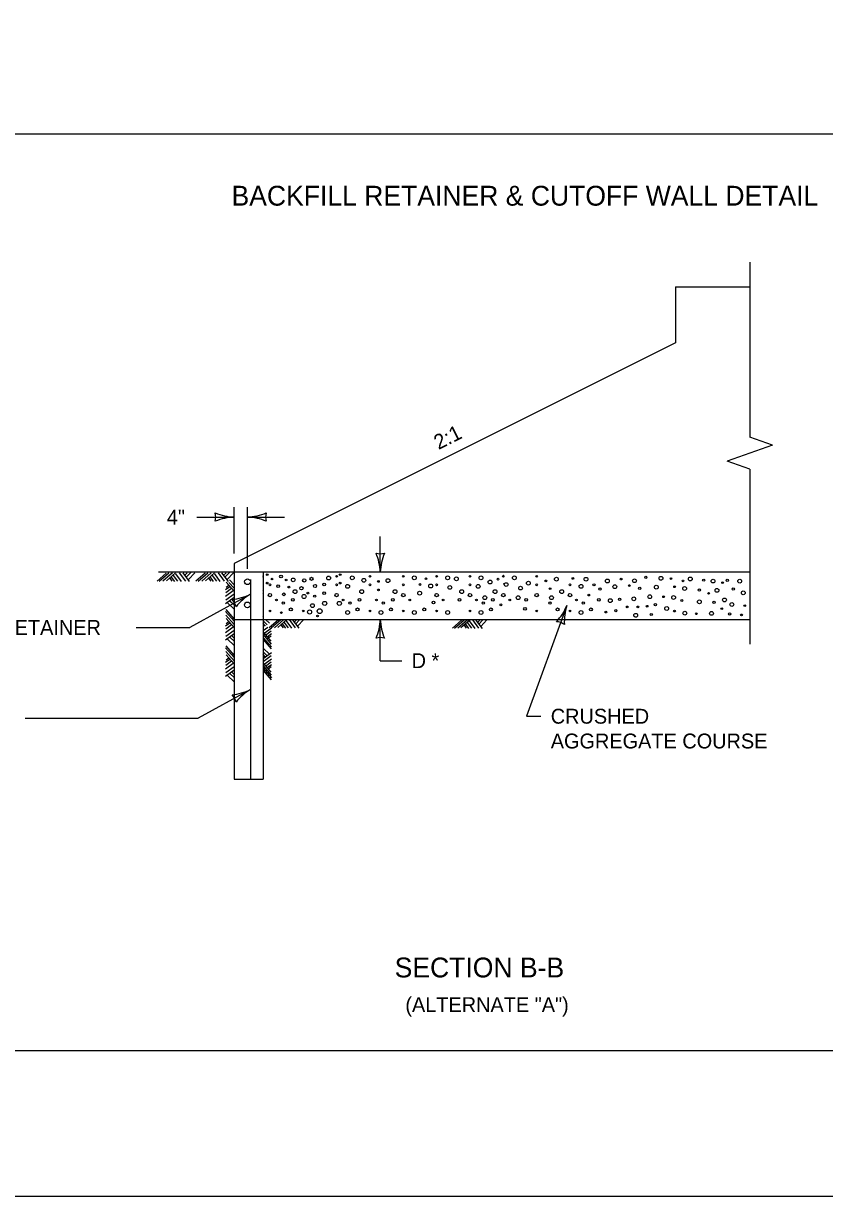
# Model space of a CAD drawing. Extents: x 49991.4 to 50021, y 49987.6 to 50011.4.
# Drawn here: x 50003.791 to 50007.022, y 49987.799 to 49992.532 of the extents above; entities that cross this region are included whole.
import ezdxf

# ---------------------------------------------------------------- set-up
doc = ezdxf.new("R2010")
doc.units = 0
for name, color, linetype in [('Level 1', 7, 'Continuous'), ('Level 2', 7, 'Continuous'), ('Level 3', 7, 'Continuous'), ('Level 6', 7, 'Continuous')]:
    doc.layers.add(name, color=color, linetype=linetype)

msp = doc.modelspace()

# ---------------------------------------------------------------- linework, layer by layer
at = {"layer": 'Level 1'}
for p, q in [((50006.4202, 49991.4692), (50006.4202, 49991.2434)), ((50006.4202, 49991.4692), (50006.7199, 49991.4692)), ((50006.4202, 49991.2434), (50004.6404, 49990.3535)), ((50004.6404, 49990.3535), (50004.6404, 49989.4831)), ((50004.367, 49990.3145), (50004.33, 49990.2823)), ((50004.3363, 49990.3188), (50004.7574, 49990.3188)), ((50004.3779, 49990.3145), (50004.339, 49990.2806)), ((50004.3917, 49990.3147), (50004.3537, 49990.2816)), ((50004.4049, 49990.3149), (50004.3686, 49990.2833)), ((50004.3814, 49990.2939), (50004.3899, 49990.2822)), ((50004.3876, 49990.2978), (50004.4001, 49990.2806)), ((50004.3954, 49990.305), (50004.4127, 49990.2812)), ((50004.405, 49990.3115), (50004.4276, 49990.2806)), ((50004.4197, 49990.3153), (50004.4442, 49990.2816)), ((50004.434, 49990.3155), (50004.46, 49990.2798)), ((50004.441, 49990.304), (50004.4518, 49990.3155)), ((50004.4475, 49990.2972), (50004.4658, 49990.3165)), ((50004.457, 49990.2881), (50004.4824, 49990.3151)), ((50004.5234, 49990.3145), (50004.4863, 49990.2823)), ((50004.5343, 49990.3145), (50004.4954, 49990.2806)), ((50004.5481, 49990.3147), (50004.51, 49990.2816)), ((50004.5613, 49990.3149), (50004.5248, 49990.2833)), ((50004.5378, 49990.2939), (50004.5463, 49990.2822)), ((50004.544, 49990.2978), (50004.5565, 49990.2806)), ((50004.5517, 49990.305), (50004.5691, 49990.2812)), ((50004.5613, 49990.3115), (50004.5838, 49990.2806)), ((50004.5759, 49990.3153), (50004.6005, 49990.2816)), ((50004.5902, 49990.3155), (50004.6164, 49990.2798)), ((50004.5973, 49990.304), (50004.6081, 49990.3155)), ((50004.6038, 49990.2972), (50004.622, 49990.3165)), ((50004.6134, 49990.2881), (50004.6388, 49990.3151)), ((50004.6404, 49990.2662), (50004.6222, 49990.2871)), ((50004.6404, 49990.3145), (50004.6404, 49990.3145)), ((50004.7072, 49990.2888), (50004.7072, 49989.4831)), ((50004.7574, 49990.3188), (50004.7574, 49989.4831)), ((50004.7574, 49990.3188), (50006.7199, 49990.3188)), ((50004.7574, 49990.3145), (50004.7574, 49990.3145)), ((50004.6236, 49990.2588), (50004.6065, 49990.2462)), ((50004.6374, 49990.2428), (50004.6065, 49990.2203)), ((50004.6308, 49990.2516), (50004.607, 49990.2343)), ((50004.6197, 49990.2644), (50004.6081, 49990.2559)), ((50004.6408, 49990.241), (50004.6092, 49990.2774)), ((50004.6406, 49990.2534), (50004.6201, 49990.2769)), ((50004.6414, 49990.2157), (50004.6057, 49990.1897)), ((50004.6411, 49990.2291), (50004.6075, 49990.2045)), ((50004.614, 49990.1941), (50004.6408, 49990.1687)), ((50004.6231, 49990.2029), (50004.6424, 49990.1845)), ((50004.6238, 49990.2012), (50004.6352, 49990.1904)), ((50004.6299, 49990.2086), (50004.6413, 49990.1978)), ((50004.6404, 49990.1197), (50004.6065, 49990.1586)), ((50004.6406, 49990.1067), (50004.6075, 49990.1448)), ((50004.6404, 49990.13), (50004.6081, 49990.167)), ((50004.6236, 49990.1123), (50004.6065, 49990.0997)), ((50004.6374, 49990.0962), (50004.6065, 49990.0736)), ((50004.6308, 49990.1051), (50004.607, 49990.0878)), ((50004.6197, 49990.1179), (50004.6081, 49990.1094)), ((50004.6408, 49990.0945), (50004.6092, 49990.1309)), ((50004.6404, 49990.1273), (50006.7199, 49990.1273)), ((50004.7746, 49990.1049), (50004.7574, 49990.1212)), ((50004.7678, 49990.1005), (50004.7574, 49990.1104)), ((50004.7574, 49990.0826), (50004.7763, 49990.0964)), ((50004.7838, 49990.1119), (50004.7675, 49990.1273)), ((50004.8194, 49990.1262), (50004.7824, 49990.0939)), ((50004.8292, 49990.1262), (50004.7903, 49990.0922)), ((50004.8415, 49990.1263), (50004.8034, 49990.0932)), ((50004.8531, 49990.1266), (50004.8167, 49990.0948)), ((50004.8297, 49990.1055), (50004.8382, 49990.0939)), ((50004.8351, 49990.1094), (50004.8476, 49990.0922)), ((50004.8417, 49990.1166), (50004.859, 49990.0928)), ((50004.85, 49990.1232), (50004.8725, 49990.0923)), ((50004.8629, 49990.1269), (50004.8874, 49990.0933)), ((50004.8755, 49990.1271), (50004.9016, 49990.0915)), ((50004.8826, 49990.1157), (50004.8934, 49990.1271)), ((50004.888, 49990.1088), (50004.9055, 49990.1273)), ((50004.8961, 49990.0996), (50004.9216, 49990.1266)), ((50005.5583, 49990.1248), (50005.5213, 49990.0925)), ((50005.5681, 49990.1248), (50005.5292, 49990.0908)), ((50005.5804, 49990.1249), (50005.5423, 49990.0918)), ((50005.592, 49990.1252), (50005.5556, 49990.0934)), ((50005.5687, 49990.1041), (50005.5771, 49990.0925)), ((50005.574, 49990.108), (50005.5865, 49990.0908)), ((50005.5806, 49990.1152), (50005.598, 49990.0914)), ((50005.5889, 49990.1218), (50005.6114, 49990.0909)), ((50005.6018, 49990.1255), (50005.6264, 49990.0919)), ((50005.6146, 49990.1257), (50005.6406, 49990.0901)), ((50005.6216, 49990.1143), (50005.6324, 49990.1257)), ((50005.6269, 49990.1074), (50005.6453, 49990.1268)), ((50005.6351, 49990.0982), (50005.6605, 49990.1252)), ((50004.6414, 49990.0692), (50004.6057, 49990.0431)), ((50004.6411, 49990.0825), (50004.6075, 49990.058)), ((50004.614, 49990.0476), (50004.6408, 49990.0221)), ((50004.6231, 49990.0562), (50004.6424, 49990.038)), ((50004.6299, 49990.0621), (50004.6413, 49990.0513)), ((50004.7574, 49990.0758), (50004.7886, 49990.04)), ((50004.7574, 49990.0658), (50004.7902, 49990.028)), ((50004.7574, 49990.055), (50004.7912, 49990.0163)), ((50004.7574, 49990.0461), (50004.7896, 49990.0092)), ((50004.7604, 49990.0706), (50004.7912, 49990.0931)), ((50004.767, 49990.0634), (50004.7907, 49990.0807)), ((50004.7742, 49990.0577), (50004.7912, 49990.0701)), ((50004.778, 49990.0531), (50004.7896, 49990.0616)), ((50004.6404, 49989.9732), (50004.6065, 49990.0121)), ((50004.6404, 49989.9835), (50004.6081, 49990.0205)), ((50004.7838, 49989.9869), (50004.7574, 49990.0118)), ((50004.6236, 49989.9656), (50004.6065, 49989.9531)), ((50004.6308, 49989.9585), (50004.607, 49989.9411)), ((50004.6406, 49989.9602), (50004.6075, 49989.9983)), ((50004.6197, 49989.9714), (50004.6081, 49989.9629)), ((50004.6408, 49989.948), (50004.6092, 49989.9843)), ((50004.7746, 49989.98), (50004.7574, 49989.9963)), ((50004.7574, 49989.9692), (50004.792, 49989.9944)), ((50004.7678, 49989.9756), (50004.7574, 49989.9855)), ((50004.7574, 49989.9577), (50004.7902, 49989.9817)), ((50004.7604, 49989.9456), (50004.7912, 49989.9681)), ((50004.767, 49989.9384), (50004.7907, 49989.9558)), ((50004.6414, 49989.9227), (50004.6057, 49989.8966)), ((50004.6374, 49989.9497), (50004.6065, 49989.9271)), ((50004.6411, 49989.936), (50004.6075, 49989.9115)), ((50004.6231, 49989.9097), (50004.6424, 49989.8915)), ((50004.6299, 49989.9156), (50004.6413, 49989.9048)), ((50004.7574, 49989.9509), (50004.7886, 49989.915)), ((50004.7574, 49989.9407), (50004.7902, 49989.903)), ((50004.7574, 49989.9301), (50004.7912, 49989.8912)), ((50004.7574, 49989.9212), (50004.7896, 49989.8841)), ((50004.7742, 49989.9327), (50004.7912, 49989.9452)), ((50004.778, 49989.9282), (50004.7896, 49989.9367)), ((50004.614, 49989.9011), (50004.6408, 49989.8755)), ((50004.6404, 49989.7217), (50004.6404, 49989.7217)), ((50004.6404, 49989.4831), (50004.7574, 49989.4831))]:
    msp.add_line(p, q, dxfattribs=at)
for points in [[(49999.3835, 49998.9992), (50016.7501, 49998.9992), (50016.7501, 49987.7988), (49999.3835, 49987.7988)], [(49999.5517, 49992.0867), (50014.5753, 49992.0867), (50014.5753, 49988.387), (49999.5517, 49988.387)]]:
    msp.add_lwpolyline(points, close=True, dxfattribs=at)
for centre, radius in [((50004.6948, 49990.2792), 0.0116), ((50004.7742, 49990.3081), 0.00346), ((50004.7936, 49990.2901), 0.00341), ((50004.8299, 49990.3001), 0.00552), ((50004.8503, 49990.2864), 0.00341), ((50004.8792, 49990.2867), 0.00765), ((50004.9236, 49990.2848), 0.00684), ((50004.9529, 49990.291), 0.00613), ((50005.0218, 49990.2942), 0.00765), ((50005.0542, 49990.3012), 0.00341), ((50005.0684, 49990.3081), 0.00346), ((50005.1172, 49990.2951), 0.00766), ((50005.1639, 49990.2852), 0.00765), ((50005.1886, 49990.3012), 0.00341), ((50005.2226, 49990.2807), 0.00346), ((50005.261, 49990.2838), 0.00765), ((50005.3231, 49990.3012), 0.00341), ((50005.3675, 49990.2951), 0.00766), ((50005.4145, 49990.2912), 0.00341), ((50005.4575, 49990.3012), 0.00341), ((50005.5019, 49990.2951), 0.00766), ((50005.5371, 49990.291), 0.00765), ((50005.5919, 49990.3012), 0.00341), ((50005.6363, 49990.2951), 0.00766), ((50005.6729, 49990.2781), 0.00765), ((50005.7049, 49990.2897), 0.00341), ((50005.7264, 49990.3012), 0.00341), ((50005.7708, 49990.2951), 0.00766), ((50005.8608, 49990.3012), 0.00341), ((50005.8978, 49990.2828), 0.00341), ((50005.9404, 49990.2895), 0.00765), ((50006.0067, 49990.2926), 0.00341), ((50006.0597, 49990.2894), 0.00766), ((50006.1459, 49990.2823), 0.00766), ((50006.2015, 49990.2898), 0.00341), ((50006.2551, 49990.2833), 0.00766), ((50006.301, 49990.297), 0.0046), ((50006.3619, 49990.2931), 0.00766), ((50006.4025, 49990.2921), 0.00341), ((50006.451, 49990.2826), 0.00341), ((50006.4803, 49990.2905), 0.00766), ((50006.5344, 49990.2857), 0.0046), ((50006.5719, 49990.2819), 0.00766), ((50006.6292, 49990.2845), 0.0046), ((50006.6795, 49990.2818), 0.00766), ((50004.7742, 49990.2737), 0.00346), ((50004.7853, 49990.2668), 0.00341), ((50004.8184, 49990.2614), 0.00552), ((50004.8618, 49990.2577), 0.00341), ((50004.8864, 49990.2393), 0.00765), ((50004.9122, 49990.2532), 0.00684), ((50004.9382, 49990.2334), 0.00341), ((50004.9672, 49990.2623), 0.00613), ((50005.0041, 49990.2678), 0.00552), ((50005.0041, 49990.2334), 0.00552), ((50005.0542, 49990.2668), 0.00341), ((50005.0684, 49990.2737), 0.00346), ((50005.0986, 49990.2607), 0.00766), ((50005.1553, 49990.2393), 0.00765), ((50005.1886, 49990.2668), 0.00341), ((50005.2226, 49990.2463), 0.00346), ((50005.2897, 49990.2393), 0.00765), ((50005.3231, 49990.2668), 0.00341), ((50005.389, 49990.2334), 0.00766), ((50005.3901, 49990.2682), 0.00341), ((50005.4334, 49990.2621), 0.00766), ((50005.4575, 49990.2668), 0.00341), ((50005.5105, 49990.2564), 0.00766), ((50005.5586, 49990.2393), 0.00765), ((50005.5919, 49990.2668), 0.00341), ((50005.6249, 49990.2607), 0.00766), ((50005.693, 49990.2393), 0.00765), ((50005.7378, 49990.2679), 0.00766), ((50005.7959, 49990.2537), 0.00765), ((50005.8274, 49990.2738), 0.00765), ((50005.8608, 49990.2668), 0.00341), ((50005.915, 49990.2512), 0.00341), ((50005.9619, 49990.2393), 0.00765), ((50005.9952, 49990.2668), 0.00341), ((50006.0397, 49990.2607), 0.00766), ((50006.0918, 49990.2668), 0.0046), ((50006.1161, 49990.2496), 0.0046), ((50006.1761, 49990.2594), 0.00766), ((50006.2344, 49990.264), 0.00341), ((50006.2766, 49990.2525), 0.0046), ((50006.3433, 49990.2573), 0.00766), ((50006.4168, 49990.2591), 0.00341), ((50006.4574, 49990.2518), 0.00766), ((50006.5171, 49990.2455), 0.0046), ((50006.5543, 49990.2324), 0.00341), ((50006.5877, 49990.2446), 0.00766), ((50006.6102, 49990.2755), 0.00341), ((50006.6535, 49990.25), 0.0046), ((50006.6939, 49990.2345), 0.00766), ((50004.6944, 49990.1858), 0.0116), ((50004.7853, 49990.2256), 0.00684), ((50004.8114, 49990.2058), 0.00341), ((50004.8389, 49990.1935), 0.0046), ((50004.8412, 49990.2286), 0.00552), ((50004.8772, 49990.2058), 0.00552), ((50004.9229, 49990.2197), 0.00824), ((50004.9566, 49990.183), 0.00766), ((50004.9658, 49990.2212), 0.0046), ((50005.0061, 49990.192), 0.00824), ((50005.0542, 49990.2256), 0.00684), ((50005.0649, 49990.192), 0.00824), ((50005.0802, 49990.2058), 0.00341), ((50005.1078, 49990.1935), 0.0046), ((50005.1461, 49990.2058), 0.00552), ((50005.2147, 49990.2058), 0.00341), ((50005.2422, 49990.1935), 0.0046), ((50005.2805, 49990.2058), 0.00552), ((50005.3231, 49990.2256), 0.00684), ((50005.3491, 49990.2058), 0.00341), ((50005.445, 49990.1952), 0.00552), ((50005.4575, 49990.2256), 0.00684), ((50005.4835, 49990.2058), 0.00341), ((50005.5494, 49990.2058), 0.00552), ((50005.5919, 49990.2256), 0.00684), ((50005.618, 49990.2058), 0.00341), ((50005.6455, 49990.1935), 0.0046), ((50005.6517, 49990.2149), 0.00766), ((50005.6838, 49990.2058), 0.00552), ((50005.7165, 49990.1861), 0.00341), ((50005.7264, 49990.2256), 0.00684), ((50005.7524, 49990.2058), 0.00341), ((50005.7861, 49990.2149), 0.00766), ((50005.8183, 49990.2058), 0.00552), ((50005.8608, 49990.2256), 0.00684), ((50005.9144, 49990.1935), 0.0046), ((50005.9205, 49990.2149), 0.00766), ((50005.9952, 49990.2256), 0.00684), ((50006.0213, 49990.2058), 0.00341), ((50006.0488, 49990.1935), 0.0046), ((50006.0709, 49990.2253), 0.00341), ((50006.1114, 49990.2058), 0.00552), ((50006.1576, 49990.203), 0.00766), ((50006.1953, 49990.2087), 0.0046), ((50006.2523, 49990.2105), 0.00766), ((50006.3168, 49990.2188), 0.00766), ((50006.3397, 49990.1871), 0.0046), ((50006.3725, 49990.2185), 0.00341), ((50006.4129, 49990.2159), 0.00766), ((50006.4461, 49990.2037), 0.0046), ((50006.5168, 49990.1985), 0.00766), ((50006.5764, 49990.1957), 0.0046), ((50006.618, 49990.2059), 0.00766), ((50006.6478, 49990.1877), 0.00766), ((50004.7853, 49990.1615), 0.00341), ((50004.8313, 49990.1548), 0.00341), ((50004.8695, 49990.1676), 0.00613), ((50004.9198, 49990.1615), 0.00341), ((50004.945, 49990.1573), 0.00824), ((50004.9773, 49990.1413), 0.00341), ((50004.9858, 49990.1605), 0.00968), ((50005.0986, 49990.1554), 0.00766), ((50005.1384, 49990.1676), 0.00613), ((50005.1886, 49990.1615), 0.00341), ((50005.233, 49990.1554), 0.00766), ((50005.2729, 49990.1676), 0.00613), ((50005.3231, 49990.1615), 0.00341), ((50005.3675, 49990.1554), 0.00766), ((50005.4073, 49990.1676), 0.00613), ((50005.4575, 49990.1615), 0.00341), ((50005.5019, 49990.1554), 0.00766), ((50005.5919, 49990.1615), 0.00341), ((50005.6363, 49990.1554), 0.00766), ((50005.6762, 49990.1676), 0.00613), ((50005.8137, 49990.17), 0.00552), ((50005.8608, 49990.1615), 0.00341), ((50005.945, 49990.1676), 0.00613), ((50005.9952, 49990.1615), 0.00341), ((50006.0397, 49990.1554), 0.00766), ((50006.0795, 49990.1676), 0.00613), ((50006.14, 49990.1569), 0.00341), ((50006.1801, 49990.1627), 0.0046), ((50006.2258, 49990.1779), 0.00341), ((50006.2603, 49990.1439), 0.00766), ((50006.2689, 49990.1779), 0.00341), ((50006.306, 49990.1805), 0.00341), ((50006.3228, 49990.1471), 0.0046), ((50006.385, 49990.1711), 0.00766), ((50006.4166, 49990.1607), 0.00341), ((50006.4581, 49990.1523), 0.00766), ((50006.5044, 49990.1502), 0.00341), ((50006.566, 49990.1516), 0.00766), ((50006.6073, 49990.1708), 0.00341), ((50006.6387, 49990.1496), 0.0046), ((50006.6867, 49990.1455), 0.00341), ((50006.6998, 49990.1826), 0.00341)]:
    msp.add_circle(centre, radius, dxfattribs=at)
for centre, radius, start, end in [((50004.7556, 49990.3002), 0.0031, 305.1264, 54.8736), ((50005.7261, 49990.302), 0.00277, 77.9755, 102.0245), ((50004.752, 49990.2393), 0.00765, 314.8637, 45.1363), ((50005.7261, 49990.2675), 0.00277, 77.9755, 102.0245), ((50004.752, 49990.134), 0.00765, 316.4208, 45.1363)]:
    msp.add_arc(centre, radius, start, end, dxfattribs=at)
at = {"layer": 'Level 3'}
for p, q in [((50004.6404, 49990.3935), (50004.6404, 49990.5801)), ((50004.6945, 49990.3308), (50004.6945, 49990.5801)), ((50004.4904, 49990.5401), (50004.6404, 49990.5401)), ((50004.6945, 49990.5401), (50004.8445, 49990.5401)), ((50005.2301, 49990.3188), (50005.2301, 49990.4617)), ((50004.7072, 49990.2295), (50004.4629, 49990.095)), ((50005.9827, 49990.1839), (50005.8202, 49989.7367)), ((50004.2464, 49990.095), (50004.4629, 49990.095)), ((50005.2301, 49989.9608), (50005.2301, 49990.1273)), ((50005.2301, 49989.9608), (50005.3166, 49989.9608)), ((50004.7072, 49989.845), (50004.4957, 49989.7285)), ((50003.7984, 49989.7285), (50004.4957, 49989.7285)), ((50005.8202, 49989.7367), (50005.8776, 49989.7367))]:
    msp.add_line(p, q, dxfattribs=at)
for centre, radius, start, end in [((50004.6496, 49990.7622), 0.2223, 247.456, 267.6395), ((50004.5122, 49990.5401), 0.0548, 342.1388, 17.8612), ((50004.6519, 49990.3073), 0.233, 92.8273, 112.0772), ((50004.683, 49990.7728), 0.233, 272.8273, 292.0772), ((50004.6853, 49990.3179), 0.2223, 67.456, 87.6395), ((50004.8227, 49990.5401), 0.0548, 162.1388, 197.8612), ((50005.2301, 49990.447), 0.0548, 252.1388, 287.8612), ((50004.9974, 49990.3073), 0.233, 2.8273, 22.0772), ((50005.4522, 49990.3096), 0.2223, 157.456, 177.6395), ((50004.608, 49990.4285), 0.2223, 276.3053, 296.4888), ((50004.5949, 49990.1677), 0.0548, 10.9881, 46.7105), ((50004.8295, 49990.0312), 0.233, 121.6766, 140.9265), ((50005.777, 49990.2683), 0.2223, 317.4863, 337.6698), ((50006.2053, 49990.1152), 0.233, 162.8576, 182.1074), ((50005.008, 49990.1364), 0.2223, 337.456, 357.6395), ((50005.4628, 49990.1387), 0.233, 182.8273, 202.0772), ((50005.9389, 49990.0633), 0.0548, 52.1691, 87.8914), ((50005.2301, 49989.999), 0.0548, 72.1388, 107.8612), ((50004.608, 49990.0439), 0.2223, 276.3053, 296.4888), ((50004.5949, 49989.7831), 0.0548, 10.9881, 46.7105), ((50004.8295, 49989.6467), 0.233, 121.6766, 140.9265)]:
    msp.add_arc(centre, radius, start, end, dxfattribs=at)
at = {"layer": 'Level 6'}
for p, q in [((50006.7199, 49991.5692), (50006.7199, 49990.863)), ((50006.8113, 49990.8306), (50006.7199, 49990.863)), ((50006.8113, 49990.8306), (50006.7199, 49990.7982)), ((50006.7199, 49990.7982), (50006.6285, 49990.7658)), ((50006.7199, 49990.7334), (50006.6285, 49990.7658)), ((50006.7199, 49990.7334), (50006.7199, 49990.0273))]:
    msp.add_line(p, q, dxfattribs=at)

# ---------------------------------------------------------------- texts
at = {"layer": 'Level 2'}
for s, height, p in [('BACKFILL RETAINER & CUTOFF WALL DETAIL', 0.08, (50004.6304, 49991.7968)), ('4"', 0.06, (50004.3697, 49990.5101)), ('BACKFILL RETAINER', 0.06, (50003.2967, 49990.065)), ('D *', 0.06, (50005.3566, 49989.9308)), ('CRUSHED', 0.06, (50005.9176, 49989.7067)), ('AGGREGATE COURSE', 0.06, (50005.9176, 49989.6067)), ('SECTION B-B', 0.08, (50005.2881, 49988.6829)), ('(ALTERNATE "A")', 0.06, (50005.3313, 49988.543))]:
    msp.add_text(s, height=height, dxfattribs=at).set_placement(p)
msp.add_text('2:1', height=0.06, rotation=26.5651, dxfattribs=at).set_placement((50005.4651, 49990.8105))

doc.saveas('drawing.dxf')
